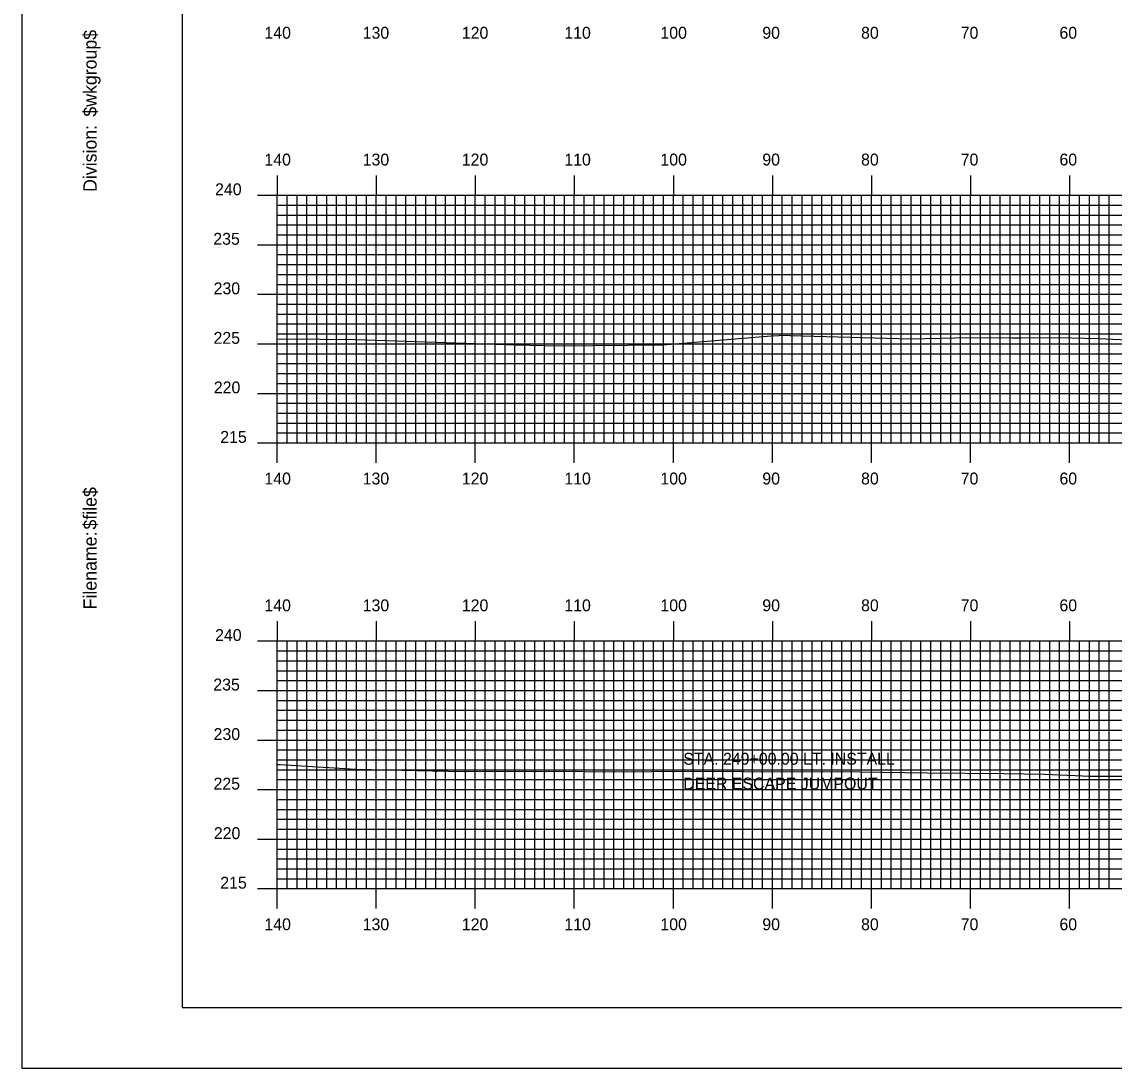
# Model space of a CAD drawing. Extents: x 1803897 to 1804240, y 442591 to 442811.
# Drawn here: x 1803896.9 to 1804007.2, y 442590.5 to 442696.2 of the extents above; entities that cross this region are included whole.
import ezdxf

# ---------------------------------------------------------------- set-up
doc = ezdxf.new("R2010")
doc.units = 0
for name, color, linetype in [('BORDER', 7, 'Continuous'), ('D_Text_Standard', 7, 'Continuous'), ('H_V ANNOTATION', 7, 'Continuous'), ('MAJOR', 7, 'Continuous'), ('MINOR', 7, 'Continuous'), ('PLOT BOUNDARY', 7, 'Continuous'), ('S_Roadway_Centerline', 7, 'Continuous')]:
    doc.layers.add(name, color=color, linetype=linetype)

msp = doc.modelspace()

# ---------------------------------------------------------------- linework, layer by layer
at = {"layer": 'BORDER'}
msp.add_lwpolyline([(1803913.05, 442596.67), (1804233.05, 442596.67), (1804233.05, 442806.67), (1803913.05, 442806.67)], close=True, dxfattribs=at)
at = {"layer": 'MAJOR'}
for p, q in [((1803922.65, 442680.67), (1803922.65, 442678.67)), ((1803932.65, 442680.67), (1803932.65, 442678.67)), ((1803942.65, 442680.67), (1803942.65, 442678.67)), ((1803952.65, 442680.67), (1803952.65, 442678.67)), ((1803962.65, 442680.67), (1803962.65, 442678.67)), ((1803972.65, 442680.67), (1803972.65, 442678.67)), ((1803982.65, 442680.67), (1803982.65, 442678.67)), ((1803992.65, 442680.67), (1803992.65, 442678.67)), ((1804002.65, 442680.67), (1804002.65, 442678.67)), ((1803920.65, 442678.67), (1803922.65, 442678.67)), ((1803922.65, 442678.67), (1804202.65, 442678.67)), ((1803922.65, 442653.67), (1803922.65, 442678.67)), ((1803922.65, 442653.67), (1803922.65, 442678.67)), ((1803922.65, 442678.67), (1804202.65, 442678.67)), ((1803932.65, 442653.67), (1803932.65, 442678.67)), ((1803942.65, 442653.67), (1803942.65, 442678.67)), ((1803952.65, 442653.67), (1803952.65, 442678.67)), ((1803962.65, 442653.67), (1803962.65, 442678.67)), ((1803972.65, 442653.67), (1803972.65, 442678.67)), ((1803982.65, 442653.67), (1803982.65, 442678.67)), ((1803992.65, 442653.67), (1803992.65, 442678.67)), ((1804002.65, 442653.67), (1804002.65, 442678.67)), ((1803920.65, 442673.67), (1803922.65, 442673.67)), ((1803922.65, 442673.67), (1804202.65, 442673.67)), ((1803920.65, 442668.67), (1803922.65, 442668.67)), ((1803922.65, 442668.67), (1804202.65, 442668.67)), ((1803920.65, 442663.67), (1803922.65, 442663.67)), ((1803922.65, 442663.67), (1804202.65, 442663.67)), ((1803920.65, 442658.67), (1803922.65, 442658.67)), ((1803922.65, 442658.67), (1804202.65, 442658.67)), ((1803920.65, 442653.67), (1803922.65, 442653.67)), ((1803922.65, 442653.67), (1804202.65, 442653.67)), ((1803922.65, 442653.67), (1804202.65, 442653.67)), ((1803922.65, 442651.66), (1803922.65, 442653.67)), ((1803932.65, 442651.66), (1803932.65, 442653.67)), ((1803942.65, 442651.66), (1803942.65, 442653.67)), ((1803952.65, 442651.66), (1803952.65, 442653.67)), ((1803962.65, 442651.66), (1803962.65, 442653.67)), ((1803972.65, 442651.66), (1803972.65, 442653.67)), ((1803982.65, 442651.66), (1803982.65, 442653.67)), ((1803992.65, 442651.66), (1803992.65, 442653.67)), ((1804002.65, 442651.66), (1804002.65, 442653.67)), ((1803922.65, 442635.67), (1803922.65, 442633.67)), ((1803932.65, 442635.67), (1803932.65, 442633.67)), ((1803942.65, 442635.67), (1803942.65, 442633.67)), ((1803952.65, 442635.67), (1803952.65, 442633.67)), ((1803962.65, 442635.67), (1803962.65, 442633.67)), ((1803972.65, 442635.67), (1803972.65, 442633.67)), ((1803982.65, 442635.67), (1803982.65, 442633.67)), ((1803992.65, 442635.67), (1803992.65, 442633.67)), ((1804002.65, 442635.67), (1804002.65, 442633.67)), ((1803920.65, 442633.67), (1803922.65, 442633.67)), ((1803922.65, 442633.67), (1804202.65, 442633.67)), ((1803922.65, 442608.67), (1803922.65, 442633.67)), ((1803922.65, 442608.67), (1803922.65, 442633.67)), ((1803922.65, 442633.67), (1804202.65, 442633.67)), ((1803932.65, 442608.67), (1803932.65, 442633.67)), ((1803942.65, 442608.67), (1803942.65, 442633.67)), ((1803952.65, 442608.67), (1803952.65, 442633.67)), ((1803962.65, 442608.67), (1803962.65, 442633.67)), ((1803972.65, 442608.67), (1803972.65, 442633.67)), ((1803982.65, 442608.67), (1803982.65, 442633.67)), ((1803992.65, 442608.67), (1803992.65, 442633.67)), ((1804002.65, 442608.67), (1804002.65, 442633.67)), ((1803920.65, 442628.67), (1803922.65, 442628.67)), ((1803922.65, 442628.67), (1804202.65, 442628.67)), ((1803920.65, 442623.67), (1803922.65, 442623.67)), ((1803922.65, 442623.67), (1804202.65, 442623.67)), ((1803920.65, 442618.67), (1803922.65, 442618.67)), ((1803922.65, 442618.67), (1804202.65, 442618.67)), ((1803920.65, 442613.67), (1803922.65, 442613.67)), ((1803922.65, 442613.67), (1804202.65, 442613.67)), ((1803920.65, 442608.67), (1803922.65, 442608.67)), ((1803922.65, 442608.67), (1804202.65, 442608.67)), ((1803922.65, 442608.67), (1804202.65, 442608.67)), ((1803922.65, 442606.66), (1803922.65, 442608.67)), ((1803932.65, 442606.66), (1803932.65, 442608.67)), ((1803942.65, 442606.66), (1803942.65, 442608.67)), ((1803952.65, 442606.66), (1803952.65, 442608.67)), ((1803962.65, 442606.66), (1803962.65, 442608.67)), ((1803972.65, 442606.66), (1803972.65, 442608.67)), ((1803982.65, 442606.66), (1803982.65, 442608.67)), ((1803992.65, 442606.66), (1803992.65, 442608.67)), ((1804002.65, 442606.66), (1804002.65, 442608.67))]:
    msp.add_line(p, q, dxfattribs=at)
at = {"layer": 'MINOR'}
for p, q in [((1803923.65, 442653.67), (1803923.65, 442678.67)), ((1803924.65, 442653.67), (1803924.65, 442678.67)), ((1803925.65, 442653.67), (1803925.65, 442678.67)), ((1803926.65, 442653.67), (1803926.65, 442678.67)), ((1803927.65, 442653.67), (1803927.65, 442678.67)), ((1803928.65, 442653.67), (1803928.65, 442678.67)), ((1803929.65, 442653.67), (1803929.65, 442678.67)), ((1803930.65, 442653.67), (1803930.65, 442678.67)), ((1803931.65, 442653.67), (1803931.65, 442678.67)), ((1803933.65, 442653.67), (1803933.65, 442678.67)), ((1803934.65, 442653.67), (1803934.65, 442678.67)), ((1803935.65, 442653.67), (1803935.65, 442678.67)), ((1803936.65, 442653.67), (1803936.65, 442678.67)), ((1803937.65, 442653.67), (1803937.65, 442678.67)), ((1803938.65, 442653.67), (1803938.65, 442678.67)), ((1803939.65, 442653.67), (1803939.65, 442678.67)), ((1803940.65, 442653.67), (1803940.65, 442678.67)), ((1803941.65, 442653.67), (1803941.65, 442678.67)), ((1803943.65, 442653.67), (1803943.65, 442678.67)), ((1803944.65, 442653.67), (1803944.65, 442678.67)), ((1803945.65, 442653.67), (1803945.65, 442678.67)), ((1803946.65, 442653.67), (1803946.65, 442678.67)), ((1803947.65, 442653.67), (1803947.65, 442678.67)), ((1803948.65, 442653.67), (1803948.65, 442678.67)), ((1803949.65, 442653.67), (1803949.65, 442678.67)), ((1803950.65, 442653.67), (1803950.65, 442678.67)), ((1803951.65, 442653.67), (1803951.65, 442678.67)), ((1803953.65, 442653.67), (1803953.65, 442678.67)), ((1803954.65, 442653.67), (1803954.65, 442678.67)), ((1803955.65, 442653.67), (1803955.65, 442678.67)), ((1803956.65, 442653.67), (1803956.65, 442678.67)), ((1803957.65, 442653.67), (1803957.65, 442678.67)), ((1803958.65, 442653.67), (1803958.65, 442678.67)), ((1803959.65, 442653.67), (1803959.65, 442678.67)), ((1803960.65, 442653.67), (1803960.65, 442678.67)), ((1803961.65, 442653.67), (1803961.65, 442678.67)), ((1803963.65, 442653.67), (1803963.65, 442678.67)), ((1803964.65, 442653.67), (1803964.65, 442678.67)), ((1803965.65, 442653.67), (1803965.65, 442678.67)), ((1803966.65, 442653.67), (1803966.65, 442678.67)), ((1803967.65, 442653.67), (1803967.65, 442678.67)), ((1803968.65, 442653.67), (1803968.65, 442678.67)), ((1803969.65, 442653.67), (1803969.65, 442678.67)), ((1803970.65, 442653.67), (1803970.65, 442678.67)), ((1803971.65, 442653.67), (1803971.65, 442678.67)), ((1803973.65, 442653.67), (1803973.65, 442678.67)), ((1803974.65, 442653.67), (1803974.65, 442678.67)), ((1803975.65, 442653.67), (1803975.65, 442678.67)), ((1803976.65, 442653.67), (1803976.65, 442678.67)), ((1803977.65, 442653.67), (1803977.65, 442678.67)), ((1803978.65, 442653.67), (1803978.65, 442678.67)), ((1803979.65, 442653.67), (1803979.65, 442678.67)), ((1803980.65, 442653.67), (1803980.65, 442678.67)), ((1803981.65, 442653.67), (1803981.65, 442678.67)), ((1803983.65, 442653.67), (1803983.65, 442678.67)), ((1803984.65, 442653.67), (1803984.65, 442678.67)), ((1803985.65, 442653.67), (1803985.65, 442678.67)), ((1803986.65, 442653.67), (1803986.65, 442678.67)), ((1803987.65, 442653.67), (1803987.65, 442678.67)), ((1803988.65, 442653.67), (1803988.65, 442678.67)), ((1803989.65, 442653.67), (1803989.65, 442678.67)), ((1803990.65, 442653.67), (1803990.65, 442678.67)), ((1803991.65, 442653.67), (1803991.65, 442678.67)), ((1803993.65, 442653.67), (1803993.65, 442678.67)), ((1803994.65, 442653.67), (1803994.65, 442678.67)), ((1803995.65, 442653.67), (1803995.65, 442678.67)), ((1803996.65, 442653.67), (1803996.65, 442678.67)), ((1803997.65, 442653.67), (1803997.65, 442678.67)), ((1803998.65, 442653.67), (1803998.65, 442678.67)), ((1803999.65, 442653.67), (1803999.65, 442678.67)), ((1804000.65, 442653.67), (1804000.65, 442678.67)), ((1804001.65, 442653.67), (1804001.65, 442678.67)), ((1804003.65, 442653.67), (1804003.65, 442678.67)), ((1804004.65, 442653.67), (1804004.65, 442678.67)), ((1804005.65, 442653.67), (1804005.65, 442678.67)), ((1804006.65, 442653.67), (1804006.65, 442678.67)), ((1803922.65, 442677.67), (1804202.65, 442677.67)), ((1803922.65, 442677.67), (1803924.66, 442677.67)), ((1803922.65, 442676.67), (1804202.65, 442676.67)), ((1803922.65, 442676.67), (1803924.66, 442676.67)), ((1803922.65, 442675.67), (1804202.65, 442675.67)), ((1803922.65, 442675.67), (1803924.66, 442675.67)), ((1803922.65, 442674.67), (1804202.65, 442674.67)), ((1803922.65, 442674.67), (1803924.66, 442674.67)), ((1803922.65, 442672.67), (1804202.65, 442672.67)), ((1803922.65, 442672.67), (1803924.66, 442672.67)), ((1803922.65, 442671.67), (1804202.65, 442671.67)), ((1803922.65, 442671.67), (1803924.66, 442671.67)), ((1803922.65, 442670.67), (1804202.65, 442670.67)), ((1803922.65, 442670.67), (1803924.66, 442670.67)), ((1803922.65, 442669.67), (1804202.65, 442669.67)), ((1803922.65, 442669.67), (1803924.66, 442669.67)), ((1803922.65, 442667.67), (1804202.65, 442667.67)), ((1803922.65, 442667.67), (1803924.66, 442667.67)), ((1803922.65, 442666.67), (1804202.65, 442666.67)), ((1803922.65, 442666.67), (1803924.66, 442666.67)), ((1803922.65, 442665.67), (1804202.65, 442665.67)), ((1803922.65, 442665.67), (1803924.66, 442665.67)), ((1803922.65, 442664.67), (1804202.65, 442664.67)), ((1803922.65, 442664.67), (1803924.66, 442664.67)), ((1803922.65, 442662.67), (1804202.65, 442662.67)), ((1803922.65, 442662.67), (1803924.66, 442662.67)), ((1803922.65, 442661.67), (1804202.65, 442661.67)), ((1803922.65, 442661.67), (1803924.66, 442661.67)), ((1803922.65, 442660.67), (1804202.65, 442660.67)), ((1803922.65, 442660.67), (1803924.66, 442660.67)), ((1803922.65, 442659.67), (1804202.65, 442659.67)), ((1803922.65, 442659.67), (1803924.66, 442659.67)), ((1803922.65, 442657.67), (1804202.65, 442657.67)), ((1803922.65, 442657.67), (1803924.66, 442657.67)), ((1803922.65, 442656.67), (1804202.65, 442656.67)), ((1803922.65, 442656.67), (1803924.66, 442656.67)), ((1803922.65, 442655.67), (1804202.65, 442655.67)), ((1803922.65, 442655.67), (1803924.66, 442655.67)), ((1803922.65, 442654.67), (1804202.65, 442654.67)), ((1803922.65, 442654.67), (1803924.66, 442654.67)), ((1803923.65, 442608.67), (1803923.65, 442633.67)), ((1803924.65, 442608.67), (1803924.65, 442633.67)), ((1803925.65, 442608.67), (1803925.65, 442633.67)), ((1803926.65, 442608.67), (1803926.65, 442633.67)), ((1803927.65, 442608.67), (1803927.65, 442633.67)), ((1803928.65, 442608.67), (1803928.65, 442633.67)), ((1803929.65, 442608.67), (1803929.65, 442633.67)), ((1803930.65, 442608.67), (1803930.65, 442633.67)), ((1803931.65, 442608.67), (1803931.65, 442633.67)), ((1803933.65, 442608.67), (1803933.65, 442633.67)), ((1803934.65, 442608.67), (1803934.65, 442633.67)), ((1803935.65, 442608.67), (1803935.65, 442633.67)), ((1803936.65, 442608.67), (1803936.65, 442633.67)), ((1803937.65, 442608.67), (1803937.65, 442633.67)), ((1803938.65, 442608.67), (1803938.65, 442633.67)), ((1803939.65, 442608.67), (1803939.65, 442633.67)), ((1803940.65, 442608.67), (1803940.65, 442633.67)), ((1803941.65, 442608.67), (1803941.65, 442633.67)), ((1803943.65, 442608.67), (1803943.65, 442633.67)), ((1803944.65, 442608.67), (1803944.65, 442633.67)), ((1803945.65, 442608.67), (1803945.65, 442633.67)), ((1803946.65, 442608.67), (1803946.65, 442633.67)), ((1803947.65, 442608.67), (1803947.65, 442633.67)), ((1803948.65, 442608.67), (1803948.65, 442633.67)), ((1803949.65, 442608.67), (1803949.65, 442633.67)), ((1803950.65, 442608.67), (1803950.65, 442633.67)), ((1803951.65, 442608.67), (1803951.65, 442633.67)), ((1803953.65, 442608.67), (1803953.65, 442633.67)), ((1803954.65, 442608.67), (1803954.65, 442633.67)), ((1803955.65, 442608.67), (1803955.65, 442633.67)), ((1803956.65, 442608.67), (1803956.65, 442633.67)), ((1803957.65, 442608.67), (1803957.65, 442633.67)), ((1803958.65, 442608.67), (1803958.65, 442633.67)), ((1803959.65, 442608.67), (1803959.65, 442633.67)), ((1803960.65, 442608.67), (1803960.65, 442633.67)), ((1803961.65, 442608.67), (1803961.65, 442633.67)), ((1803963.65, 442608.67), (1803963.65, 442633.67)), ((1803964.65, 442608.67), (1803964.65, 442633.67)), ((1803965.65, 442608.67), (1803965.65, 442633.67)), ((1803966.65, 442608.67), (1803966.65, 442633.67)), ((1803967.65, 442608.67), (1803967.65, 442633.67)), ((1803968.65, 442608.67), (1803968.65, 442633.67)), ((1803969.65, 442608.67), (1803969.65, 442633.67)), ((1803970.65, 442608.67), (1803970.65, 442633.67)), ((1803971.65, 442608.67), (1803971.65, 442633.67)), ((1803973.65, 442608.67), (1803973.65, 442633.67)), ((1803974.65, 442608.67), (1803974.65, 442633.67)), ((1803975.65, 442608.67), (1803975.65, 442633.67)), ((1803976.65, 442608.67), (1803976.65, 442633.67)), ((1803977.65, 442608.67), (1803977.65, 442633.67)), ((1803978.65, 442608.67), (1803978.65, 442633.67)), ((1803979.65, 442608.67), (1803979.65, 442633.67)), ((1803980.65, 442608.67), (1803980.65, 442633.67)), ((1803981.65, 442608.67), (1803981.65, 442633.67)), ((1803983.65, 442608.67), (1803983.65, 442633.67)), ((1803984.65, 442608.67), (1803984.65, 442633.67)), ((1803985.65, 442608.67), (1803985.65, 442633.67)), ((1803986.65, 442608.67), (1803986.65, 442633.67)), ((1803987.65, 442608.67), (1803987.65, 442633.67)), ((1803988.65, 442608.67), (1803988.65, 442633.67)), ((1803989.65, 442608.67), (1803989.65, 442633.67)), ((1803990.65, 442608.67), (1803990.65, 442633.67)), ((1803991.65, 442608.67), (1803991.65, 442633.67)), ((1803993.65, 442608.67), (1803993.65, 442633.67)), ((1803994.65, 442608.67), (1803994.65, 442633.67)), ((1803995.65, 442608.67), (1803995.65, 442633.67)), ((1803996.65, 442608.67), (1803996.65, 442633.67)), ((1803997.65, 442608.67), (1803997.65, 442633.67)), ((1803998.65, 442608.67), (1803998.65, 442633.67)), ((1803999.65, 442608.67), (1803999.65, 442633.67)), ((1804000.65, 442608.67), (1804000.65, 442633.67)), ((1804001.65, 442608.67), (1804001.65, 442633.67)), ((1804003.65, 442608.67), (1804003.65, 442633.67)), ((1804004.65, 442608.67), (1804004.65, 442633.67)), ((1804005.65, 442608.67), (1804005.65, 442633.67)), ((1804006.65, 442608.67), (1804006.65, 442633.67)), ((1803922.65, 442632.67), (1804202.65, 442632.67)), ((1803922.65, 442632.67), (1803924.66, 442632.67)), ((1803922.65, 442631.67), (1804202.65, 442631.67)), ((1803922.65, 442631.67), (1803924.66, 442631.67)), ((1803922.65, 442630.67), (1804202.65, 442630.67)), ((1803922.65, 442630.67), (1803924.66, 442630.67)), ((1803922.65, 442629.67), (1804202.65, 442629.67)), ((1803922.65, 442629.67), (1803924.66, 442629.67)), ((1803922.65, 442627.67), (1804202.65, 442627.67)), ((1803922.65, 442627.67), (1803924.66, 442627.67)), ((1803922.65, 442626.67), (1804202.65, 442626.67)), ((1803922.65, 442626.67), (1803924.66, 442626.67)), ((1803922.65, 442625.67), (1804202.65, 442625.67)), ((1803922.65, 442625.67), (1803924.66, 442625.67)), ((1803922.65, 442624.67), (1804202.65, 442624.67)), ((1803922.65, 442624.67), (1803924.66, 442624.67)), ((1803922.65, 442622.67), (1804202.65, 442622.67)), ((1803922.65, 442622.67), (1803924.66, 442622.67)), ((1803922.65, 442621.67), (1804202.65, 442621.67)), ((1803922.65, 442621.67), (1803924.66, 442621.67)), ((1803922.65, 442620.67), (1804202.65, 442620.67)), ((1803922.65, 442620.67), (1803924.66, 442620.67)), ((1803922.65, 442619.67), (1804202.65, 442619.67)), ((1803922.65, 442619.67), (1803924.66, 442619.67)), ((1803922.65, 442617.67), (1804202.65, 442617.67)), ((1803922.65, 442617.67), (1803924.66, 442617.67)), ((1803922.65, 442616.67), (1804202.65, 442616.67)), ((1803922.65, 442616.67), (1803924.66, 442616.67)), ((1803922.65, 442615.67), (1804202.65, 442615.67)), ((1803922.65, 442615.67), (1803924.66, 442615.67)), ((1803922.65, 442614.67), (1804202.65, 442614.67)), ((1803922.65, 442614.67), (1803924.66, 442614.67)), ((1803922.65, 442612.67), (1804202.65, 442612.67)), ((1803922.65, 442612.67), (1803924.66, 442612.67)), ((1803922.65, 442611.67), (1804202.65, 442611.67)), ((1803922.65, 442611.67), (1803924.66, 442611.67)), ((1803922.65, 442610.67), (1804202.65, 442610.67)), ((1803922.65, 442610.67), (1803924.66, 442610.67)), ((1803922.65, 442609.67), (1804202.65, 442609.67)), ((1803922.65, 442609.67), (1803924.66, 442609.67))]:
    msp.add_line(p, q, dxfattribs=at)
at = {"layer": 'PLOT BOUNDARY'}
msp.add_lwpolyline([(1803896.87, 442590.55), (1804236.87, 442590.55), (1804236.87, 442810.55), (1803896.87, 442810.55)], close=True, dxfattribs=at)
at = {"layer": 'S_Roadway_Centerline'}
for points in [[(1803922.65, 442664.18), (1803926.98, 442664.14), (1803930.56, 442664.09), (1803946.76, 442663.57), (1803951, 442663.46), (1803961.63, 442663.58), (1803972.52, 442664.46), (1803974.08, 442664.53), (1803974.44, 442664.52), (1803986.59, 442664.16), (1803992.58, 442664.3), (1803996.9, 442664.27), (1803997.73, 442664.27), (1804002.52, 442664.31), (1804002.87, 442664.28), (1804005.59, 442664.19), (1804009.95, 442663.99)], [(1803922.65, 442621.2), (1803922.93, 442621.19), (1803930.58, 442620.73), (1803941.42, 442620.49), (1803951.63, 442620.52), (1803955.77, 442620.47), (1803965.04, 442620.54), (1803974.59, 442620.47), (1803979.2, 442620.5), (1803988.31, 442620.37), (1803996.03, 442620.28), (1804000.17, 442620.22), (1804004.74, 442620.03), (1804015.78, 442620.02)]]:
    msp.add_lwpolyline(points, dxfattribs=at)

# ---------------------------------------------------------------- texts
at = {"layer": 'BORDER'}
for s, p in [('$wkgroup$', (1803904.42, 442686.6)), ('Division:', (1803904.42, 442679)), ('$file$', (1803904.42, 442644.92)), ('Filename:', (1803904.42, 442636.86))]:
    msp.add_text(s, height=1.339, rotation=90, dxfattribs=at).set_placement(p)
at = {"layer": 'D_Text_Standard'}
for s, p in [('STA. 249+00.00 LT. INSTALL ', (1803963.65, 442621.18)), ('DEER ESCAPE JUMPOUT', (1803963.65, 442618.68))]:
    msp.add_text(s, height=1.2, dxfattribs=at).set_placement(p)
at = {"layer": 'H_V ANNOTATION'}
for s, p in [('140', (1803921.36, 442694.47)), ('130', (1803931.28, 442694.47)), ('120', (1803941.29, 442694.47)), ('110', (1803951.64, 442694.47)), ('100', (1803961.34, 442694.47)), ('90', (1803971.63, 442694.47)), ('80', (1803981.6, 442694.47)), ('70', (1803991.66, 442694.47)), ('60', (1804001.63, 442694.47)), ('140', (1803921.36, 442681.67)), ('130', (1803931.28, 442681.67)), ('120', (1803941.29, 442681.67)), ('110', (1803951.64, 442681.67)), ('100', (1803961.34, 442681.67)), ('90', (1803971.63, 442681.67)), ('80', (1803981.6, 442681.67)), ('70', (1803991.66, 442681.67)), ('60', (1804001.63, 442681.67)), ('240', (1803916.38, 442678.67)), ('235', (1803916.2, 442673.67)), ('230', (1803916.23, 442668.67)), ('225', (1803916.22, 442663.67)), ('220', (1803916.25, 442658.67)), ('215', (1803916.9, 442653.67)), ('140', (1803921.36, 442649.47)), ('130', (1803931.28, 442649.47)), ('120', (1803941.29, 442649.47)), ('110', (1803951.64, 442649.47)), ('100', (1803961.34, 442649.47)), ('90', (1803971.63, 442649.47)), ('80', (1803981.6, 442649.47)), ('70', (1803991.66, 442649.47)), ('60', (1804001.63, 442649.47)), ('140', (1803921.36, 442636.67)), ('130', (1803931.28, 442636.67)), ('120', (1803941.29, 442636.67)), ('110', (1803951.64, 442636.67)), ('100', (1803961.34, 442636.67)), ('90', (1803971.63, 442636.67)), ('80', (1803981.6, 442636.67)), ('70', (1803991.66, 442636.67)), ('60', (1804001.63, 442636.67)), ('240', (1803916.38, 442633.67)), ('235', (1803916.2, 442628.67)), ('230', (1803916.23, 442623.67)), ('225', (1803916.22, 442618.67)), ('220', (1803916.25, 442613.67)), ('215', (1803916.9, 442608.67)), ('140', (1803921.36, 442604.47)), ('130', (1803931.28, 442604.47)), ('120', (1803941.29, 442604.47)), ('110', (1803951.64, 442604.47)), ('100', (1803961.34, 442604.47)), ('90', (1803971.63, 442604.47)), ('80', (1803981.6, 442604.47)), ('70', (1803991.66, 442604.47)), ('60', (1804001.63, 442604.47))]:
    msp.add_text(s, height=1.2, dxfattribs=at).set_placement(p)
at = {"layer": 'MAJOR'}
for p in [(1803922.65, 442653.67), (1803922.65, 442608.67)]:
    msp.add_text('-', height=0.012, dxfattribs=at).set_placement(p)

doc.saveas('drawing.dxf')
